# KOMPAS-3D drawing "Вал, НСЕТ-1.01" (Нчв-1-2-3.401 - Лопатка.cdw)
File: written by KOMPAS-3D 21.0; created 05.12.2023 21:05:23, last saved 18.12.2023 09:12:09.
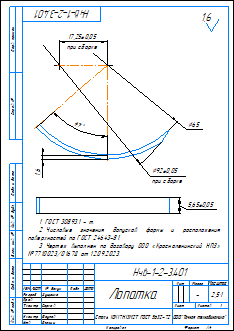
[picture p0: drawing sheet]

Sheet 1: A4, portrait

Document properties: Полное имя файла: D:\Точная технодинамика\04.12.2023\для отправки\центробежный насос нчв-1-2-3 (6) (готово)\Нчв-1-2-3.401 - Лопатка.cdw; Автор: zaycev_alexandr@mail.ru; Параметр неуказанной шероховатости: 1,6

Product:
- Part/product: Вал  | designation НСЕТ-1.01
    Материал: Сталь 10Х17Н13М2Т(ЭИ448) ГОСТ 5632-2014 (density 8000 kg/m3)
    Масса: 2.553371
    Форматы листов документа: A4
    source file: НСЕТ-1.01 - Вал.cdw

Title block, sheet 1: Наименование: Лопатка; designation: Нчв-1-2-3 . 401; Материал: Сталь 10Х17Н13М2Т ГОСТ 5632-72; scale: 2,5:1; Количество листов документа: 1; organisation: ООО "Точная технодинамика"; Форматы листов документа: A4; stored path: E:\Точная технодинамика\Задания\ООО «Красноленинский НПЗ»\Чертежи\НСЕТ-1.01 - Вал.cdw; Разработал: Дущенко; Т. контр.: Серков; Н. контр.: Юсупов; Утвердил: Елагин

Views: Разрез 6, Вид 7
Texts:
  при сборке
  Версия вида
  Тип вида
  Матрица вида
  Точка разреза
  ElectricLineNodes
  es-vk-info-doc
  es-ov-info-doc
  es-tx-info-doc
Dimensions and other numbers on the sheet: 1,6; 92; 65; 5,65±0,05; 17,25; 2,5:1; 1

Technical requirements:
  ГОСТ 30893.1 - m.
  Числовые значения допусков формы и расположения
  поверхностей по ГОСТ 24643-81.
  Чертеж выполнен по договору ООО «Красноленинский НПЗ»
  №7710023/0167Д от 12.09.2023.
